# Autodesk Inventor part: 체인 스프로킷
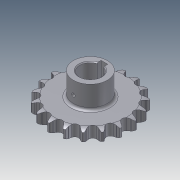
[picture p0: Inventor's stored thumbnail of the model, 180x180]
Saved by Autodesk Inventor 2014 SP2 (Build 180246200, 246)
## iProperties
Created: 2014-07
Part Number: 체인 스프로킷
Material: 강
Document SubType Name: Modeling
Designer: KYOUNG IL JANG
Density: 7.85 g/cm^3
Appearance: 강철
Mass: 738.599 g
Surface Area: 236.854 cm^2
Volume: 94.089 cm^3
CustomPartVersion: 1
Company: 한국ATC센터
Author: KYOUNG IL JANG
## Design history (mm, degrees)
sketch "이론적 톱니 프로파일"
  geometry: L1 (0, 0)-(0, 45.567); L2 (0, 0)-(14.795, 43.098); L3 (0, 45.567)-(14.795, 43.098); L4 (0, 45.567)-(5.661, 50.015); L5 (5.661, 50.015)-(-5.141, 45.406); L6 (-12.428, 43.493)-(-5.573, 46.417); L7 (-5.141, 45.406)-(-5.573, 46.417); L8 (5.573, 46.417)-(5.141, 45.406); L9 (0, 0)-(8.138, 48.771); A1 r 45.567 centre (0, 0) between (0, 45.567) and (14.795, 43.098); A2 r 49.445 centre (0, 0) between (7.302, 48.903) and (-7.302, 48.903); A3 r 4.545 centre (0, 45.567) between (-3.574, 42.758) and (3.574, 42.758); A4 r 7.453 centre (12.428, 43.493) between (7.302, 48.903) and (5.573, 46.417); A5 r 7.453 centre (-12.428, 43.493) between (-5.573, 46.417) and (-7.302, 48.903); A6 r 11.745 centre (5.661, 50.015) between (-5.141, 45.406) and (-3.574, 42.758); A7 r 11.745 centre (-5.661, 50.015) between (3.574, 42.758) and (5.141, 45.406); 2 further points
  constraints: 18 end point, 15 point on circle, 7 centre point, 3 coincident, 3 point on line, 3 symmetric about line, 3 tangent, 1 equal radius, 1 midpoint, 1 parallel, 1 vertical, 1 other
  dimensions: "d0" = 91.13301 diameter of A1 (computed from da_p, da_z); "d2" = 18.9474 deg angle of L2 L1 (computed from da_z); "d3" = 4.545 radius of A3 (= 0.5 x da_Dr + da_SC); "d10" = 128.158 deg angle of L4 L1 (computed from da_z); "d11" = 15.0526 deg angle of L5 L4 (computed from da_z); "d12" = 7.2 distance of L3.start L4.end (= 0.8 x da_Dr); "d13" = 11.745 distance of L4.end L5.end (= 1.3 x da_Dr + da_SC); "d14" = 12.6 distance of A4.centre L1.end (= 1.4 x da_Dr); "d23" = 4.5 distance from line of L9.end L3 (= da_Ha)
sketch "톱니 프로파일"
  geometry: L1 (0, 0)-(0, 45.567); L2 (0, 45.567)-(4.203, 43.837); L3 (0, 45.567)-(-4.203, 43.837); A1 r 4.545 centre (0, 45.567) between (-4.203, 43.837) and (4.203, 43.837); A2 r 22.68 centre (25.176, 35.206) between (7.12, 48.93) and (4.203, 43.837); A3 r 22.68 centre (-25.176, 35.206) between (-4.203, 43.837) and (-7.12, 48.93); A4 r 49.445 centre (0, 0) between (-7.12, 48.93) and (7.12, 48.93) reference; 1 further point
  constraints: 9 point on circle, 6 end point, 3 centre point, 2 tangent, 1 coincident, 1 equal radius, 1 vertical, 1 other
  dimensions: "d44" = 135.263 deg angle of L3 L2 (= da_Alfa); "d45" = 22.68 radius of A2 (= da_Re); "d46" = 4.545 radius of A1 (= da_Ri)
sketch "단면 프로파일"
  geometry: L1 (49.445, 0)-(-49.445, 0) reference; L2 (33.265, 6.65)-(-33.265, 6.65); L3 (-33.265, 6.65)-(-33.265, -6.65); L4 (-33.265, -6.65)-(33.265, -6.65); L5 (33.265, -6.65)-(33.265, 6.65); L6 (33.265, 6.65)-(49.445, 6.65); L7 (49.445, 6.65)-(49.445, -6.65); L8 (49.445, -6.65)-(33.265, -6.65); L9 (33.265, -6.65)-(33.265, 6.65); L10 (42.183, 6.65)-(0, 6.65); L11 (0, 6.65)-(0, -6.65); L12 (0, -6.65)-(42.183, -6.65); L13 (0, 6.65)-(0, -6.65); L14 (49.445, 4.775)-(49.445, -4.775); A1 r 15 centre (42.183, -8.35) between (49.445, 4.775) and (42.183, 6.65); A2 r 15 centre (42.183, 8.35) between (42.183, -6.65) and (49.445, -4.775); 2 further points
  constraints: 26 end point, 7 midpoint, 5 perpendicular, 4 parallel, 4 point on circle, 3 point on line, 3 symmetric about line, 2 centre point, 2 horizontal, 2 tangent, 1 collinear, 1 other
  dimensions: "d30" = 13.3 distance between parallel lines of L8 L6 (= da_Bf); "d31" = 66.53007 distance between parallel lines of L3 L5 (= da_Ds); "d32" = 13.3 distance between parallel lines of L4 L2 (= da_Bs); "d33" = 1.875 distance from line of L14.start L6 (= da_Ba); "d34" = 15 radius of A1 (= da_Rx); "d43" = 6.65 distance between parallel lines of L4 L1 (computed from da_k, da_pt, da_Bs)
revolve "슈라우드" stored, may be unused: angle "d36" = 90 deg
revolve "스트랜드" stored, may be unused: angle "d37" = 90 deg
extrude "이론적 톱니" cut sketch "이론적 톱니 프로파일" stored distance "d18" = 10; taper "d19" = 0 deg; dims "d49" = 0, "form_type" = 0 [user parameter]
extrude "톱니" cut sketch "톱니 프로파일" stored distance "d47" = 10; taper "d48" = 0 deg; dims "d50" = 10, "form_type" = 0 [user parameter]
node "타이밍 평면"
node "작업 평면3"
sketch "스케치5"
  geometry: C1 r 20 at (0, -45.567); 1 further point
  constraints: 1 centre point, 1 coincident
  dimensions: "d52" = 40 diameter of C1
extrude "돌출4" join sketch "스케치5" stored distance "d53" = 10; taper "d54" = 0 deg
sketch "스케치6"
  geometry: L1 (4, 11.843)-(4, 16.5); L2 (4, 16.5)-(-4, 16.5); L3 (-4, 16.5)-(-4, 11.843); A1 r 12.5 centre (0, 0) between (4, 11.843) and (-4, 11.843); 1 further point
  constraints: 6 end point, 2 parallel, 2 point on circle, 1 centre point, 1 coincident, 1 perpendicular, 1 vertical
  dimensions: "d55" = 25 diameter of A1; "d56" = 29 dimension on A1 L2 (computed from d55); "d57" = 8 distance of L1.end L2.end
extrude "돌출5" cut sketch "스케치6" stored distance "d58" = 10; taper "d59" = 0 deg
fillet "모깎기2" dims "d60" = 3
chamfer "모따기1" distance "d61" = 1; stored, may be unused: second distance "d62" = 2, angle "d63" = 45 deg
node "작업 평면4"
sketch "스케치7"
  geometry: L1 (-13.5, -13.3)-(13.5, -13.3) reference; 4 further points
  constraints: 1 vertical alignment
  dimensions: "d65" = 25 distance from line of point (0, 11.7) L1
hole "구멍1" sketch "스케치7" at (0, 11.7) diameter "d66" = 4.134; stored, may be unused: countersink angle "d70" = 90 deg, drill point angle "d72" = 118 deg; dims "d67" = 6, "d68" = 4, "d69" = 2, "d71" = 8
body "Solid1"
pattern_linear "스트랜드 패턴" dims "d40" = 24 (= da_pt)
pattern_circular "톱니 패턴" dims angle "d21" = 360 deg
other parameters: "da_p" = 15 [user parameter; used in 1 equation term], "da_Dr" = 9 [user parameter; used in 4 equation terms], "da_SC" = 0.045 [user parameter; used in 2 equation terms], "da_Ha" = 4.5 [user parameter; used in 1 equation term], "da_pt" = 24 [user parameter; used in 2 equation terms], "da_Bf" = 13.3 [user parameter; used in 1 equation term], "d28" = 0, "d29" = 0, "da_Ba" = 1.875 [user parameter; used in 1 equation term], "da_Rx" = 15 [user parameter; used in 1 equation term], "da_Ra" = 0.6 [user parameter], "da_Bs" = 13.3 [user parameter; used in 2 equation terms], "da_Ds" = 66.53007 [user parameter; used in 1 equation term], "d42" = 0, "da_Re" = 22.68 [user parameter; used in 1 equation term], "da_Ri" = 4.545 [user parameter; used in 1 equation term], "da_Alfa" = 135.263 deg [user parameter; used in 1 equation term]
